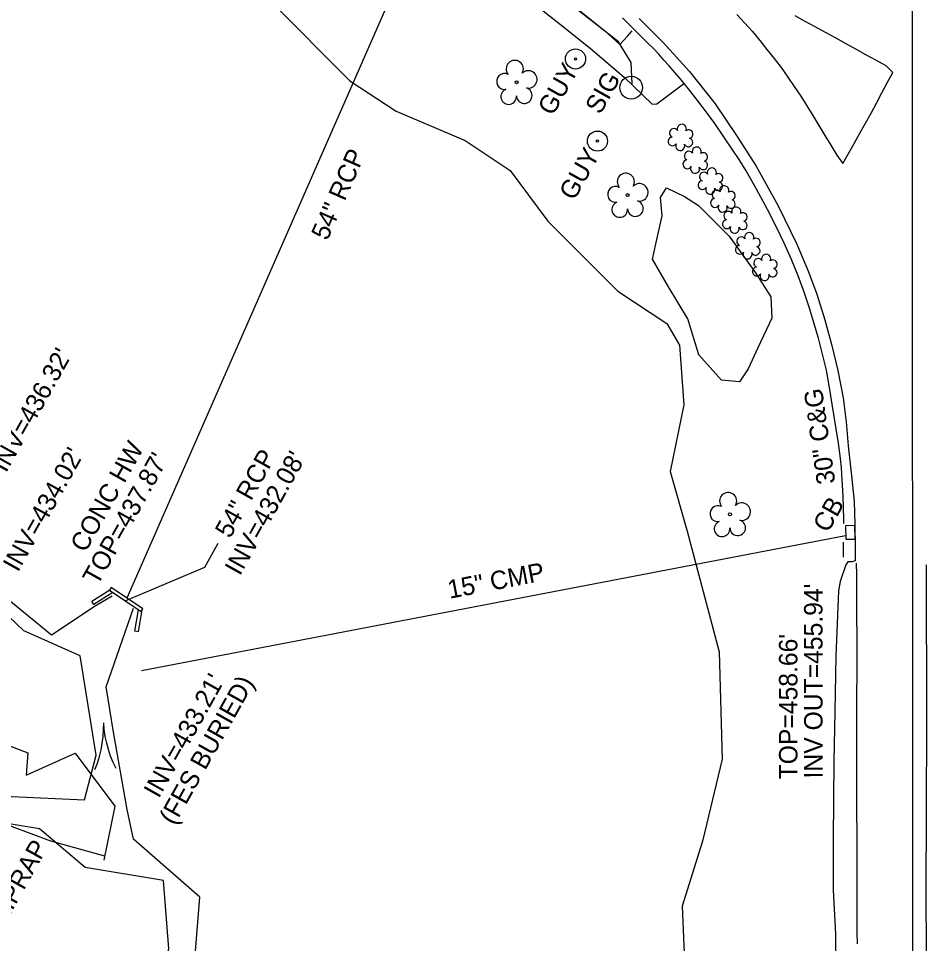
# Model space of a CAD drawing. Extents: x 2074109 to 2077820, y 741079 to 746031.
# Drawn here: x 2074923.4 to 2075120.4, y 743369.7 to 743570.1 of the extents above; entities that cross this region are included whole.
import ezdxf

# ---------------------------------------------------------------- set-up
doc = ezdxf.new("R2010")
doc.units = 0
for name, color, linetype in [('Exist Horizontal Alignment', 7, 'Continuous'), ('Exist Hydro Jurisdictional Stream or Body of Water', 7, 'Continuous'), ('Exist Hydro Stream Flow Arrow CELL', 7, 'Continuous'), ('Exist Hydro Stream or Body of Water', 7, 'Continuous'), ('Exist Other Culture Anchor (Guy Wire) CELL', 7, 'Continuous'), ('Exist Other Culture Anchor (Guy Wire) Text', 7, 'Continuous'), ('Exist Other Culture Area Outline', 7, 'Continuous'), ('Exist Other Culture Area Outline Text', 7, 'Continuous'), ('Exist Roads Curbs', 7, 'Continuous'), ('Exist Roads Curbs Text', 7, 'Continuous'), ('Exist Roads EOP', 7, 'Continuous'), ('Exist Roads EOP Other', 7, 'Continuous'), ('Exist Roads EOT', 7, 'Continuous'), ('Exist Structure Major Bridge WW', 7, 'Continuous'), ('Exist Structure Minor Catch Basin', 7, 'Continuous'), ('Exist Structure Minor Catch Basin Text', 7, 'Continuous'), ('Exist Structure Minor Drop Inlet Top Elevation', 7, 'Continuous'), ('Exist Structure Minor Head and End Wall', 7, 'Continuous'), ('Exist Structure Minor Head and End Wall Text', 7, 'Continuous'), ('Exist Structure Minor Pipes CMP 15 Inch', 7, 'Continuous'), ('Exist Structure Minor Pipes CMP 15 Inch Invert', 7, 'Continuous'), ('Exist Structure Minor Pipes CMP 15 Inch Text', 7, 'Continuous'), ('Exist Structure Minor Pipes HDPE 12 Inch Invert', 7, 'Continuous'), ('Exist Structure Minor Pipes RCP 30 Inch Invert', 7, 'Continuous'), ('Exist Structure Minor Pipes RCP 54 Inch', 7, 'Continuous'), ('Exist Structure Minor Pipes RCP 54 Inch Invert', 7, 'Continuous'), ('Exist Structure Minor Pipes RCP 54 Inch Leader', 7, 'Continuous'), ('Exist Structure Minor Pipes RCP 54 Inch Text', 7, 'Continuous'), ('Exist Utilities Other Pole CELL', 7, 'Continuous'), ('Exist Utilities Other Pole Text', 7, 'Continuous'), ('Exist Utilities Power UG Cable SUE LOS B', 7, 'Continuous'), ('Exist Vegetation Hedge Row', 7, 'Continuous'), ('Exist Vegetation Shrub CELL', 7, 'Continuous'), ('Exist Vegetation Tree CELL', 7, 'Continuous'), ('Exist Vegetation Woods Line', 7, 'Continuous')]:
    doc.layers.add(name, color=color, linetype=linetype)

msp = doc.modelspace()

# ---------------------------------------------------------------- linework, layer by layer
at = {"layer": 'Exist Horizontal Alignment'}
msp.add_line((2075117.31, 743260.76), (2075117.13, 743617.06), dxfattribs=at)
at = {"layer": 'Exist Hydro Jurisdictional Stream or Body of Water'}
for points in [[(2074903.25, 743054.49), (2074909.76, 743105.79), (2074914.28, 743166.15), (2074918.88, 743241.03), (2074923.86, 743273.74), (2074937.88, 743289.43), (2074950.67, 743320.84), (2074961.52, 743365.31), (2074962.73, 743379.75), (2074948.34, 743392.28), (2074946.95, 743398.74), (2074944.01, 743415.47), (2074942.43, 743425.27), (2074948.3, 743442.32)], [(2074900.6, 743092.38), (2074902.83, 743108.44), (2074909.01, 743167.83), (2074911.03, 743221.44), (2074912.87, 743241.26), (2074919.25, 743277.85), (2074929.03, 743287.53), (2074943.81, 743324.69), (2074955.99, 743368.53), (2074954.81, 743383.32), (2074937.89, 743386.14), (2074927.97, 743394.52), (2074919.08, 743396.01), (2074906.45, 743395.37), (2074895.43, 743399.83)]]:
    msp.add_lwpolyline(points, dxfattribs=at)
at = {"layer": 'Exist Hydro Stream Flow Arrow CELL'}
msp.add_line((2074942.07, 743412.49), (2074942.07, 743412.49), dxfattribs=at)
for points in [[(2074939.98, 743407.41), (2074940.52, 743408.77), (2074940.93, 743410.21), (2074941.31, 743411.64), (2074941.57, 743413.06), (2074941.75, 743414.53), (2074941.85, 743416.03), (2074941.87, 743417.49)], [(2074944.55, 743407.59), (2074943.9, 743408.9), (2074943.38, 743410.31), (2074942.89, 743411.7), (2074942.52, 743413.1), (2074942.22, 743414.55), (2074942, 743416.03), (2074941.87, 743417.49)]]:
    msp.add_lwpolyline(points, dxfattribs=at)
at = {"layer": 'Exist Hydro Stream or Body of Water'}
msp.add_lwpolyline([(2074893.58, 743401.62), (2074909.77, 743404.96), (2074921.91, 743401.56), (2074937.7, 743400.84), (2074940.25, 743410.49), (2074936.77, 743432), (2074924.54, 743437.42), (2074918.23, 743443.43), (2074920.07, 743445.2), (2074930.57, 743436.54), (2074940.04, 743442.87), (2074943.73, 743445.05)], dxfattribs=at)
at = {"layer": 'Exist Other Culture Anchor (Guy Wire) CELL'}
for centre, radius in [((2075044.14, 743561.33), 2.18), ((2075044.14, 743561.33), 0.24), ((2075048.89, 743543.54), 2.18), ((2075048.89, 743543.54), 0.24)]:
    msp.add_circle(centre, radius, dxfattribs=at)
at = {"layer": 'Exist Other Culture Area Outline'}
msp.add_lwpolyline([(2074942.13, 743388.63), (2074930.42, 743391.89), (2074917.57, 743396.62), (2074908.62, 743395.05), (2074909.1, 743405.7), (2074915.86, 743408.6), (2074921.09, 743412.7), (2074925.44, 743411.02), (2074925.04, 743406.16), (2074935.71, 743410.92), (2074944.31, 743399.48), (2074941.93, 743387.73)], dxfattribs=at)
at = {"layer": 'Exist Roads Curbs'}
for points in [[(2075102.3, 743460.68), (2075102.29, 743461.62), (2075102.12, 743466.63), (2075101.96, 743470.18), (2075101.79, 743472.74), (2075101.59, 743474.79), (2075101.13, 743478.07), (2075100.15, 743484.33), (2075099.13, 743490.6), (2075098.51, 743493.94), (2075098.05, 743495.95), (2075097.49, 743498.21), (2075096.79, 743500.84), (2075095.89, 743503.93), (2075094.84, 743507.31), (2075093.69, 743510.78), (2075092.4, 743514.31), (2075090.93, 743517.88), (2075089.35, 743521.43), (2075087.68, 743524.92), (2075085.75, 743528.69), (2075083.36, 743533.13), (2075081.12, 743537.12), (2075079.64, 743539.54), (2075078.26, 743541.59), (2075076.31, 743544.47), (2075074.33, 743547.33), (2075072.88, 743549.33), (2075071.59, 743551.01), (2075070.14, 743552.9), (2075068.6, 743554.85), (2075067.09, 743556.73), (2075065.67, 743558.43), (2075064.45, 743559.84), (2075063.31, 743561.1), (2075062.17, 743562.35), (2075061.01, 743563.56), (2075059.83, 743564.74), (2075058.64, 743565.92), (2075057.42, 743567.16), (2075056.02, 743568.57), (2075054.3, 743570.23)], [(2075102.21, 743453.43), (2075102.24, 743456.62)]]:
    msp.add_lwpolyline(points, dxfattribs=at)
at = {"layer": 'Exist Roads EOP'}
msp.add_lwpolyline([(2075057.95, 743570.11), (2075063.14, 743564.87), (2075068.85, 743558.63), (2075074.43, 743551.6), (2075079.07, 743544.78), (2075083.29, 743538.1), (2075088.08, 743529.54), (2075092.12, 743521.23), (2075094.67, 743515.24), (2075096.44, 743510.35), (2075098.15, 743504.84), (2075099.68, 743499.26), (2075100.97, 743493.87), (2075102.16, 743487.94), (2075102.84, 743482.72), (2075103.26, 743477.52), (2075103.97, 743471.05), (2075104.51, 743465.47), (2075104.71, 743460.52), (2075104.73, 743455.28), (2075104.79, 743453.72), (2075104.76, 743452.58), (2075104.06, 743452.39), (2075103.19, 743452.35), (2075102.7, 743451.7), (2075101.48, 743448.11), (2075101.13, 743446.09), (2075100.55, 743432.05), (2075100.33, 743419.87), (2075100.11, 743409.21), (2075099.99, 743392.27), (2075100.02, 743381.33), (2075100.46, 743371.73), (2075100.72, 743344.66)], dxfattribs=at)
at = {"layer": 'Exist Roads EOP Other'}
for points in [[(2074736.15, 743743.52), (2074745.36, 743738.39), (2074764.63, 743727.87), (2074783.88, 743717.41), (2074799.06, 743709.14), (2074820.47, 743697.56), (2074844.02, 743684.7), (2074871.78, 743669.61), (2074897.44, 743655.45), (2074932.64, 743636.17), (2074957.19, 743622.75), (2074981.37, 743609.53), (2075002.24, 743597.98), (2075030.68, 743582.18), (2075033.44, 743580.49), (2075037.68, 743577.54), (2075043.96, 743572.63), (2075050.45, 743567.5), (2075053.78, 743564.46), (2075055.44, 743566.25), (2075056.43, 743567.41)], [(2074733.88, 743739.15), (2074742.99, 743734.08), (2074762.28, 743723.55), (2074781.53, 743713.09), (2074796.71, 743704.81), (2074818.12, 743693.23), (2074841.67, 743680.38), (2074869.42, 743665.29), (2074895.07, 743651.14), (2074930.28, 743631.85), (2074954.82, 743618.43), (2074979, 743605.22), (2074999.86, 743593.68), (2075028.28, 743577.89), (2075030.72, 743576.39), (2075034.73, 743573.6), (2075040.92, 743568.76), (2075047.31, 743563.7), (2075054.69, 743557.36), (2075060.75, 743551.55), (2075061.79, 743551.62), (2075067.53, 743555.92)]]:
    msp.add_lwpolyline(points, dxfattribs=at)
at = {"layer": 'Exist Roads EOT'}
for points in [[(2075079.1, 743570.97), (2075080.8, 743569.13), (2075082.49, 743567.29), (2075084.07, 743565.35), (2075085.62, 743563.39), (2075087.17, 743561.43), (2075088.71, 743559.47), (2075090.15, 743557.42), (2075091.56, 743555.36), (2075092.98, 743553.3), (2075094.31, 743551.19), (2075095.61, 743549.05), (2075096.91, 743546.92), (2075098.21, 743544.78), (2075099.5, 743542.65), (2075100.8, 743540.51), (2075102.09, 743538.67), (2075103.31, 743540.85), (2075104.53, 743543.03), (2075105.75, 743545.22), (2075106.97, 743547.4), (2075108.19, 743549.58), (2075109.4, 743551.77), (2075110.56, 743553.98), (2075111.72, 743556.19), (2075112.89, 743558.4), (2075111.45, 743559.84), (2075109.26, 743561.05), (2075107.07, 743562.25), (2075104.88, 743563.46), (2075102.69, 743564.67), (2075100.5, 743565.88), (2075098.31, 743567.07), (2075096.11, 743568.26), (2075093.91, 743569.46), (2075091.72, 743570.65)], [(2075105.01, 743452.1), (2075105.02, 743449.6), (2075105.03, 743447.1), (2075105.05, 743444.6), (2075105.06, 743442.1), (2075105.08, 743439.6), (2075105.09, 743437.1), (2075105.1, 743434.6), (2075105.1, 743432.1), (2075105.09, 743429.6), (2075105.09, 743427.1), (2075105.08, 743424.6), (2075105.08, 743422.1), (2075105.07, 743419.6), (2075105.06, 743417.1), (2075105.06, 743414.61), (2075105.05, 743412.11), (2075105.05, 743409.61), (2075105.05, 743407.11), (2075105.06, 743404.61), (2075105.07, 743402.11), (2075105.07, 743399.61), (2075105.08, 743397.11), (2075105.09, 743394.61), (2075105.09, 743392.11), (2075105.1, 743389.61), (2075105.11, 743387.12), (2075105.12, 743384.62), (2075105.12, 743382.12), (2075105.13, 743379.62), (2075105.14, 743377.12), (2075105.14, 743374.62), (2075105.15, 743372.12), (2075105.16, 743369.62)], [(2075107.36, 742950.39), (2075109.71, 742970.82), (2075112.38, 742997.13), (2075114.36, 743020.92), (2075115.78, 743038.63), (2075117.18, 743060.58), (2075118.26, 743089.99), (2075119, 743113.88), (2075119.54, 743143.19), (2075119.9, 743172.64), (2075120.3, 743201.98), (2075120.44, 743232.24), (2075120.36, 743270.24), (2075120.21, 743304.86), (2075120.36, 743344.86), (2075120.15, 743380.31), (2075120.28, 743417.16), (2075120.24, 743451.73)]]:
    msp.add_lwpolyline(points, dxfattribs=at)
at = {"layer": 'Exist Structure Major Bridge WW'}
msp.add_line((2074943.17, 743446.24), (2074939.29, 743443.81), dxfattribs=at)
msp.add_lwpolyline([(2074943.88, 743445.76), (2074939.71, 743443.14), (2074939.29, 743443.81)], dxfattribs=at)
at = {"layer": 'Exist Structure Minor Catch Basin'}
msp.add_lwpolyline([(2075102.79, 743457.24), (2075102.75, 743460.29), (2075104.64, 743460.31), (2075104.68, 743457.26)], close=True, dxfattribs=at)
at = {"layer": 'Exist Structure Minor Head and End Wall'}
msp.add_line((2074949.43, 743437.25), (2074950.23, 743441.99), dxfattribs=at)
for points in [[(2074950.35, 743442.18), (2074943.47, 743446.84), (2074943.12, 743446.27)], [(2074943.12, 743446.27), (2074950.01, 743441.62), (2074950.35, 743442.18)], [(2074949.43, 743437.25), (2074948.65, 743437.38), (2074949.43, 743442.01)]]:
    msp.add_lwpolyline(points, dxfattribs=at)
at = {"layer": 'Exist Structure Minor Pipes CMP 15 Inch'}
msp.add_line((2075102.69, 743458.03), (2074950.1, 743428.79), dxfattribs=at)
at = {"layer": 'Exist Structure Minor Pipes RCP 54 Inch'}
msp.add_line((2075074.8, 743735.81), (2074946.91, 743444.52), dxfattribs=at)
at = {"layer": 'Exist Structure Minor Pipes RCP 54 Inch Leader'}
msp.add_lwpolyline([(2074946.56, 743443.94), (2074963.77, 743451.22), (2074966.71, 743456.45)], dxfattribs=at)
at = {"layer": 'Exist Utilities Other Pole CELL'}
msp.add_circle((2075056.21, 743555.11), 2.46, dxfattribs=at)
at = {"layer": 'Exist Utilities Power UG Cable SUE LOS B'}
msp.add_lwpolyline([(2075056.41, 743555.92), (2075056.18, 743560.57), (2075053.43, 743565.07), (2075034.01, 743580.27), (2075019.01, 743590.04), (2075019.25, 743592.31)], dxfattribs=at)
at = {"layer": 'Exist Vegetation Hedge Row'}
msp.add_lwpolyline([(2075070.77, 743529.59), (2075077.44, 743522.91), (2075083.15, 743514.99), (2075086.5, 743509.81), (2075086.73, 743505.14), (2075083.69, 743498.78), (2075081.54, 743494.2), (2075079.67, 743491.41), (2075075.77, 743491.75), (2075070.89, 743497.24), (2075068.49, 743505.03), (2075064.28, 743511.99), (2075060.8, 743517.95), (2075061.92, 743522.89), (2075062.9, 743527.36), (2075062.59, 743531.31), (2075063.83, 743533.41), (2075067.77, 743531.55), (2075070.77, 743529.59)], dxfattribs=at)
at = {"layer": 'Exist Vegetation Shrub CELL'}
for p, q in [((2075066.96, 743544.17), (2075066.96, 743544.17)), ((2075070.18, 743539.22), (2075070.18, 743539.22)), ((2075073.46, 743534.69), (2075073.46, 743534.69)), ((2075076.17, 743530.83), (2075076.17, 743530.83)), ((2075078.76, 743526.22), (2075078.76, 743526.22)), ((2075081.56, 743520.69), (2075081.56, 743520.69)), ((2075085.24, 743515.99), (2075085.24, 743515.99))]:
    msp.add_line(p, q, dxfattribs=at)
for centre, radius, start, end in [((2075065.48, 743545.29), 0.968, 35.8908, 245.4216), ((2075067.19, 743546.21), 0.99, 334.8391, 200.4717), ((2075065.16, 743543.46), 0.955, 95.1099, 327.9534), ((2075068.6, 743543.24), 0.937, 204.9913, 73.4601), ((2075068.63, 743545.04), 0.929, 284.4567, 126.0861), ((2075066.83, 743542.48), 0.984, 151.2797, 21.387), ((2075070.41, 743541.26), 0.99, 334.8391, 200.4717), ((2075068.7, 743540.35), 0.968, 35.8908, 245.4216), ((2075071.85, 743540.09), 0.929, 284.4567, 126.0861), ((2075068.38, 743538.51), 0.955, 95.1099, 327.9534), ((2075071.82, 743538.29), 0.937, 204.9913, 73.4601), ((2075070.05, 743537.54), 0.984, 151.2797, 21.387), ((2075071.97, 743535.82), 0.968, 35.8908, 245.4216), ((2075073.68, 743536.73), 0.99, 334.8391, 200.4717), ((2075075.13, 743535.56), 0.929, 284.4567, 126.0861), ((2075071.65, 743533.99), 0.955, 95.1099, 327.9534), ((2075075.09, 743533.76), 0.937, 204.9913, 73.4601), ((2075073.33, 743533.01), 0.984, 151.2797, 21.387), ((2075074.69, 743531.96), 0.968, 35.8908, 245.4216), ((2075076.4, 743532.87), 0.99, 334.8391, 200.4717), ((2075077.85, 743531.7), 0.929, 284.4567, 126.0861), ((2075074.37, 743530.13), 0.955, 95.1099, 327.9534), ((2075077.81, 743529.9), 0.937, 204.9913, 73.4601), ((2075076.04, 743529.15), 0.984, 151.2797, 21.387), ((2075077.27, 743527.35), 0.968, 35.8908, 245.4216), ((2075078.98, 743528.26), 0.99, 334.8391, 200.4717), ((2075076.95, 743525.52), 0.955, 95.1099, 327.9534), ((2075080.39, 743525.29), 0.937, 204.9913, 73.4601), ((2075080.43, 743527.09), 0.929, 284.4567, 126.0861), ((2075078.63, 743524.54), 0.984, 151.2797, 21.387), ((2075080.08, 743521.82), 0.968, 35.8908, 245.4216), ((2075081.79, 743522.73), 0.99, 334.8391, 200.4717), ((2075083.23, 743521.56), 0.929, 284.4567, 126.0861), ((2075079.76, 743519.99), 0.955, 95.1099, 327.9534), ((2075083.2, 743519.76), 0.937, 204.9913, 73.4601), ((2075081.43, 743519.01), 0.984, 151.2797, 21.387), ((2075083.76, 743517.12), 0.968, 35.8908, 245.4216), ((2075085.47, 743518.03), 0.99, 334.8391, 200.4717), ((2075083.44, 743515.28), 0.955, 95.1099, 327.9534), ((2075086.91, 743516.86), 0.929, 284.4567, 126.0861), ((2075085.11, 743514.3), 0.984, 151.2797, 21.387), ((2075086.88, 743515.06), 0.937, 204.9913, 73.4601)]:
    msp.add_arc(centre, radius, start, end, dxfattribs=at)
at = {"layer": 'Exist Vegetation Tree CELL'}
for p, q in [((2075031.36, 743556.3), (2075031.36, 743556.3)), ((2075055.43, 743531.83), (2075055.43, 743531.83)), ((2075077.62, 743462.67), (2075077.62, 743462.67))]:
    msp.add_line(p, q, dxfattribs=at)
for centre in [(2075031.36, 743556.3), (2075055.43, 743531.83), (2075077.62, 743462.67)]:
    msp.add_circle(centre, 0.326, dxfattribs=at)
for centre, radius, start, end in [((2075030.98, 743559.17), 1.86, 330.1651, 219.7134), ((2075028.76, 743556.45), 1.73, 62.6636, 279.3457), ((2075033.91, 743556.89), 1.9, 257.1011, 134.1999), ((2075029.66, 743553.18), 1.69, 111.5671, 6.231), ((2075033.03, 743553.4), 1.7, 181.2822, 74.56), ((2075055.05, 743534.7), 1.86, 330.1651, 219.7134), ((2075057.98, 743532.42), 1.9, 257.1011, 134.1999), ((2075052.83, 743531.98), 1.73, 62.6636, 279.3457), ((2075053.73, 743528.71), 1.69, 111.5671, 6.231), ((2075057.11, 743528.93), 1.7, 181.2822, 74.56), ((2075077.23, 743465.54), 1.86, 330.1651, 219.7134), ((2075075.01, 743462.82), 1.73, 62.6636, 279.3457), ((2075080.17, 743463.26), 1.9, 257.1011, 134.1999), ((2075075.91, 743459.55), 1.69, 111.5671, 6.231), ((2075079.29, 743459.77), 1.7, 181.2822, 74.56)]:
    msp.add_arc(centre, radius, start, end, dxfattribs=at)
at = {"layer": 'Exist Vegetation Woods Line'}
msp.add_lwpolyline([(2074905.1, 743624.9), (2074958.77, 743586.73), (2074978.04, 743573.88), (2074995.23, 743556.58), (2075005.25, 743550.04), (2075020.25, 743543.63), (2075030.01, 743537.15), (2075038.16, 743526.18), (2075053.34, 743511.04), (2075063.92, 743504.02), (2075066.65, 743499.3), (2075067.63, 743486.43), (2075064.69, 743471.93), (2075068.31, 743459.01), (2075075.3, 743432.9), (2075075.94, 743409.67), (2075071.68, 743391.87), (2075067.29, 743377.76), (2075068.15, 743357.32)], dxfattribs=at)

# ---------------------------------------------------------------- texts
at = {"layer": 'Exist Other Culture Anchor (Guy Wire) Text'}
for p in [(2075039.23, 743548.83), (2075043.86, 743530.46)]:
    msp.add_text('GUY', height=4, rotation=60.742, dxfattribs=at).set_placement(p)
at = {"layer": 'Exist Other Culture Area Outline Text'}
msp.add_text('RIPRAP', height=4, rotation=60.742, dxfattribs=at).set_placement((2074920.16, 743373.3))
at = {"layer": 'Exist Roads Curbs Text'}
msp.add_text('30" C&G', height=4, rotation=98.0683, dxfattribs=at).set_placement((2075100.48, 743469.47))
at = {"layer": 'Exist Structure Minor Catch Basin Text'}
msp.add_text('CB', height=4, rotation=60.742, dxfattribs=at).set_placement((2075098.87, 743458.49))
at = {"layer": 'Exist Structure Minor Drop Inlet Top Elevation'}
msp.add_text("TOP=458.66'", height=4, rotation=90.0314, dxfattribs=at).set_placement((2075092.25, 743405.26))
at = {"layer": 'Exist Structure Minor Head and End Wall Text'}
for s, p in [('CONC HW', (2074937.9, 743454.19)), ("TOP=437.87'", (2074940.56, 743447.07))]:
    msp.add_text(s, height=4, rotation=60.742, dxfattribs=at).set_placement(p)
at = {"layer": 'Exist Structure Minor Pipes CMP 15 Inch Invert'}
for s, rotation, p in [("INV OUT=455.94'", 90.0314, (2075097.7, 743405.46)), ("INV=433.21'", 60.742, (2074953.81, 743400.97)), ('(FES BURIED)', 60.742, (2074957.19, 743395.14))]:
    msp.add_text(s, height=4, rotation=rotation, dxfattribs=at).set_placement(p)
at = {"layer": 'Exist Structure Minor Pipes CMP 15 Inch Text'}
msp.add_text('15" CMP', height=4, rotation=10.8476, dxfattribs=at).set_placement((2075016.84, 743444.38))
at = {"layer": 'Exist Structure Minor Pipes HDPE 12 Inch Invert'}
msp.add_text("INV=436.32'", height=4, rotation=60.7411, dxfattribs=at).set_placement((2074920.71, 743471.53))
at = {"layer": 'Exist Structure Minor Pipes RCP 30 Inch Invert'}
msp.add_text("INV=434.02'", height=4, rotation=60.7411, dxfattribs=at).set_placement((2074923.28, 743449.98))
at = {"layer": 'Exist Structure Minor Pipes RCP 54 Inch Invert'}
for s, p in [('54" RCP', (2074969.26, 743457.27)), ("INV=432.08'", (2074971.38, 743449.19))]:
    msp.add_text(s, height=4, rotation=60.742, dxfattribs=at).set_placement(p)
at = {"layer": 'Exist Structure Minor Pipes RCP 54 Inch Text'}
msp.add_text('54" RCP', height=4, rotation=66.2963, dxfattribs=at).set_placement((2074990.35, 743521.82))
at = {"layer": 'Exist Utilities Other Pole Text'}
msp.add_text('SIG', height=4, rotation=60.5812, dxfattribs=at).set_placement((2075049.51, 743549.11))

doc.saveas('drawing.dxf')
